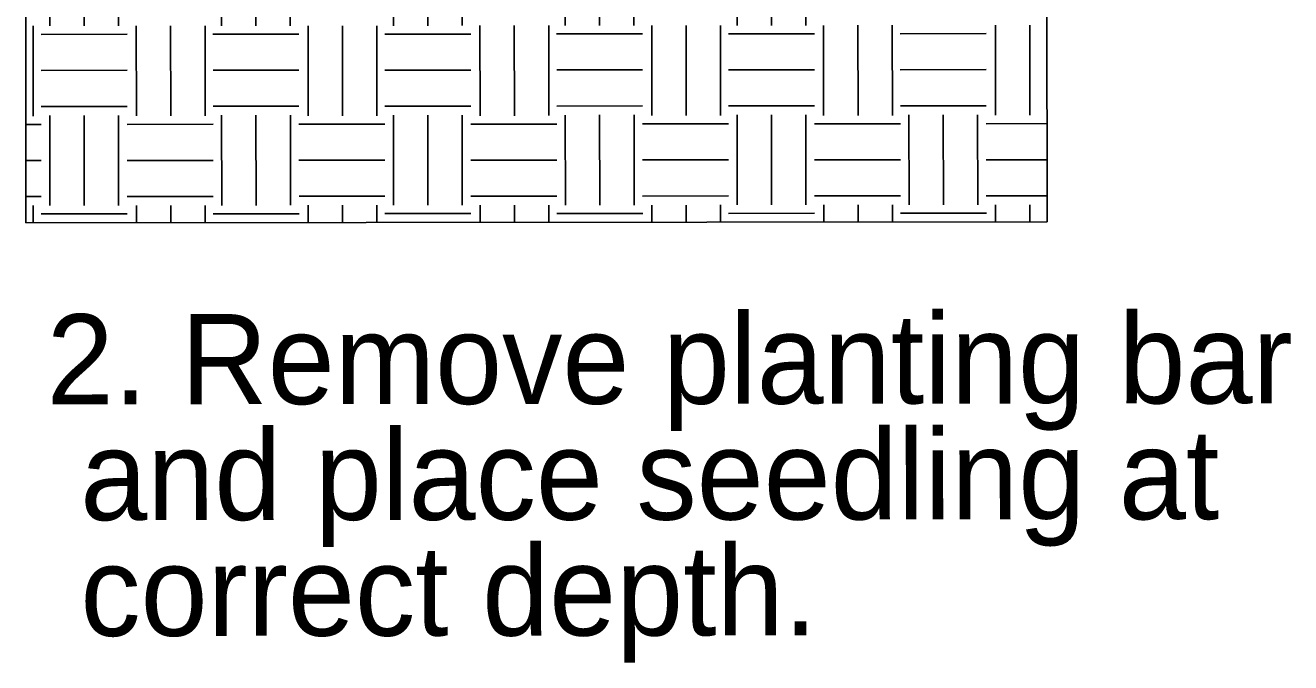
# Model space of a CAD drawing. Extents: x 816132 to 817815, y 885694 to 886789.
# Drawn here: x 816765 to 816859.1, y 886354.3 to 886401.8 of the extents above; entities that cross this region are included whole.
import ezdxf

# ---------------------------------------------------------------- set-up
doc = ezdxf.new("R2010")
doc.units = 0
doc.layers.add('Silt Fence Coir Fiber Wattle Break Detail CELL', color=7, linetype='Continuous')

msp = doc.modelspace()

# ---------------------------------------------------------------- linework, layer by layer
at = {"layer": 'Silt Fence Coir Fiber Wattle Break Detail CELL'}
for p, q in [((816765.014, 886440.944), (816765.053, 886387.062)), ((816765.014, 886440.944), (816765.053, 886387.062)), ((816840.991, 886441.003), (816841.029, 886387.121)), ((816766.827, 886408.409), (816766.832, 886401.705)), ((816769.382, 886408.411), (816769.388, 886401.707)), ((816771.939, 886408.413), (816771.944, 886401.709)), ((816779.608, 886408.419), (816779.613, 886401.715)), ((816782.165, 886408.421), (816782.169, 886401.717)), ((816784.721, 886408.423), (816784.726, 886401.719)), ((816792.391, 886408.429), (816792.395, 886401.725)), ((816794.947, 886408.431), (816794.952, 886401.727)), ((816797.504, 886408.433), (816797.509, 886401.729)), ((816805.173, 886408.439), (816805.178, 886401.735)), ((816807.73, 886408.441), (816807.735, 886401.737)), ((816810.286, 886408.443), (816810.291, 886401.739)), ((816817.956, 886408.449), (816817.961, 886401.745)), ((816820.512, 886408.451), (816820.517, 886401.747)), ((816823.069, 886408.453), (816823.073, 886401.749)), ((816765.601, 886401.704), (816765.605, 886395)), ((816773.269, 886401.71), (816773.275, 886395.006)), ((816775.826, 886401.712), (816775.831, 886395.008)), ((816778.382, 886401.714), (816778.388, 886395.01)), ((816786.052, 886401.72), (816786.057, 886395.016)), ((816788.608, 886401.722), (816788.613, 886395.018)), ((816791.165, 886401.724), (816791.169, 886395.02)), ((816798.834, 886401.73), (816798.839, 886395.026)), ((816801.391, 886401.732), (816801.395, 886395.028)), ((816803.947, 886401.734), (816803.952, 886395.03)), ((816811.617, 886401.74), (816811.621, 886395.036)), ((816814.173, 886401.742), (816814.178, 886395.038)), ((816816.73, 886401.744), (816816.735, 886395.04)), ((816824.399, 886401.75), (816824.404, 886395.046)), ((816826.956, 886401.752), (816826.961, 886395.048)), ((816829.512, 886401.754), (816829.517, 886395.05)), ((816837.181, 886401.76), (816837.187, 886395.056)), ((816839.737, 886401.762), (816839.743, 886395.058)), ((816766.192, 886401.081), (816772.583, 886401.086)), ((816778.975, 886401.091), (816785.366, 886401.096)), ((816791.757, 886401.101), (816798.148, 886401.106)), ((816804.539, 886401.111), (816810.931, 886401.116)), ((816817.321, 886401.121), (816823.713, 886401.126)), ((816830.104, 886401.131), (816836.495, 886401.137)), ((816766.194, 886398.399), (816772.586, 886398.404)), ((816778.977, 886398.41), (816785.367, 886398.415)), ((816791.759, 886398.42), (816798.15, 886398.425)), ((816804.542, 886398.429), (816810.932, 886398.434)), ((816817.323, 886398.439), (816823.715, 886398.444)), ((816830.106, 886398.449), (816836.497, 886398.455)), ((816766.197, 886395.717), (816772.587, 886395.722)), ((816778.978, 886395.728), (816785.37, 886395.733)), ((816791.761, 886395.738), (816798.152, 886395.743)), ((816804.543, 886395.748), (816810.934, 886395.753)), ((816817.326, 886395.757), (816823.716, 886395.763)), ((816830.108, 886395.768), (816836.499, 886395.773)), ((816766.836, 886395.048), (816766.841, 886388.344)), ((816769.393, 886395.049), (816769.397, 886388.346)), ((816771.949, 886395.051), (816771.954, 886388.348)), ((816779.618, 886395.058), (816779.623, 886388.354)), ((816782.174, 886395.06), (816782.179, 886388.356)), ((816784.731, 886395.062), (816784.735, 886388.358)), ((816792.4, 886395.068), (816792.405, 886388.364)), ((816794.957, 886395.07), (816794.961, 886388.366)), ((816797.513, 886395.072), (816797.518, 886388.367)), ((816805.183, 886395.078), (816805.187, 886388.374)), ((816807.739, 886395.08), (816807.744, 886388.375)), ((816810.296, 886395.082), (816810.301, 886388.378)), ((816817.965, 886395.088), (816817.97, 886388.383)), ((816820.522, 886395.09), (816820.527, 886388.386)), ((816823.078, 886395.092), (816823.083, 886388.388)), ((816830.748, 886395.098), (816830.753, 886388.394)), ((816833.304, 886395.1), (816833.309, 886388.396)), ((816835.86, 886395.103), (816835.865, 886388.398)), ((816765.048, 886394.376), (816766.197, 886394.377)), ((816772.589, 886394.382), (816778.98, 886394.387)), ((816785.37, 886394.392), (816791.762, 886394.397)), ((816798.153, 886394.402), (816804.545, 886394.407)), ((816810.935, 886394.412), (816817.326, 886394.417)), ((816823.718, 886394.422), (816830.109, 886394.427)), ((816836.5, 886394.432), (816841.024, 886394.435)), ((816765.05, 886391.694), (816766.199, 886391.695)), ((816772.59, 886391.7), (816778.981, 886391.705)), ((816785.373, 886391.71), (816791.764, 886391.715)), ((816798.155, 886391.721), (816804.546, 886391.726)), ((816810.937, 886391.731), (816817.329, 886391.735)), ((816823.72, 886391.74), (816830.11, 886391.745)), ((816836.502, 886391.75), (816841.026, 886391.754)), ((816765.051, 886389.013), (816766.201, 886389.014)), ((816772.592, 886389.019), (816778.983, 886389.024)), ((816785.375, 886389.028), (816791.765, 886389.033)), ((816798.157, 886389.039), (816804.548, 886389.044)), ((816810.939, 886389.049), (816817.33, 886389.054)), ((816823.721, 886389.059), (816830.113, 886389.064)), ((816836.504, 886389.069), (816841.028, 886389.072)), ((816765.61, 886388.343), (816765.611, 886387.062)), ((816773.28, 886388.349), (816773.28, 886387.068)), ((816775.836, 886388.351), (816775.837, 886387.07)), ((816778.392, 886388.353), (816778.394, 886387.072)), ((816786.061, 886388.359), (816786.063, 886387.078)), ((816788.618, 886388.361), (816788.619, 886387.081)), ((816791.174, 886388.362), (816791.175, 886387.083)), ((816798.844, 886388.369), (816798.845, 886387.089)), ((816801.4, 886388.37), (816801.401, 886387.091)), ((816803.957, 886388.373), (816803.958, 886387.092)), ((816811.626, 886388.378), (816811.627, 886387.099)), ((816814.183, 886388.381), (816814.184, 886387.1)), ((816816.739, 886388.383), (816816.74, 886387.102)), ((816824.409, 886388.389), (816824.41, 886387.108)), ((816826.965, 886388.391), (816826.966, 886387.11)), ((816829.522, 886388.393), (816829.523, 886387.113)), ((816837.191, 886388.399), (816837.192, 886387.118)), ((816839.747, 886388.401), (816839.749, 886387.121)), ((816765.053, 886387.062), (816841.029, 886387.121)), ((816766.202, 886387.72), (816772.593, 886387.724)), ((816778.984, 886387.729), (816785.375, 886387.734)), ((816791.767, 886387.74), (816798.158, 886387.745)), ((816804.549, 886387.75), (816810.94, 886387.755)), ((816817.331, 886387.76), (816823.723, 886387.765)), ((816830.113, 886387.77), (816836.505, 886387.774))]:
    msp.add_line(p, q, dxfattribs=at)

# ---------------------------------------------------------------- texts
for s, p in [('2. Remove planting bar ', (816766.607, 886373.549)), (' and place seedling at ', (816766.614, 886364.929)), (' correct depth.', (816766.62, 886356.309))]:
    msp.add_text(s, height=6.70408, rotation=0.04504, dxfattribs=at).set_placement(p)

doc.saveas('drawing.dxf')
